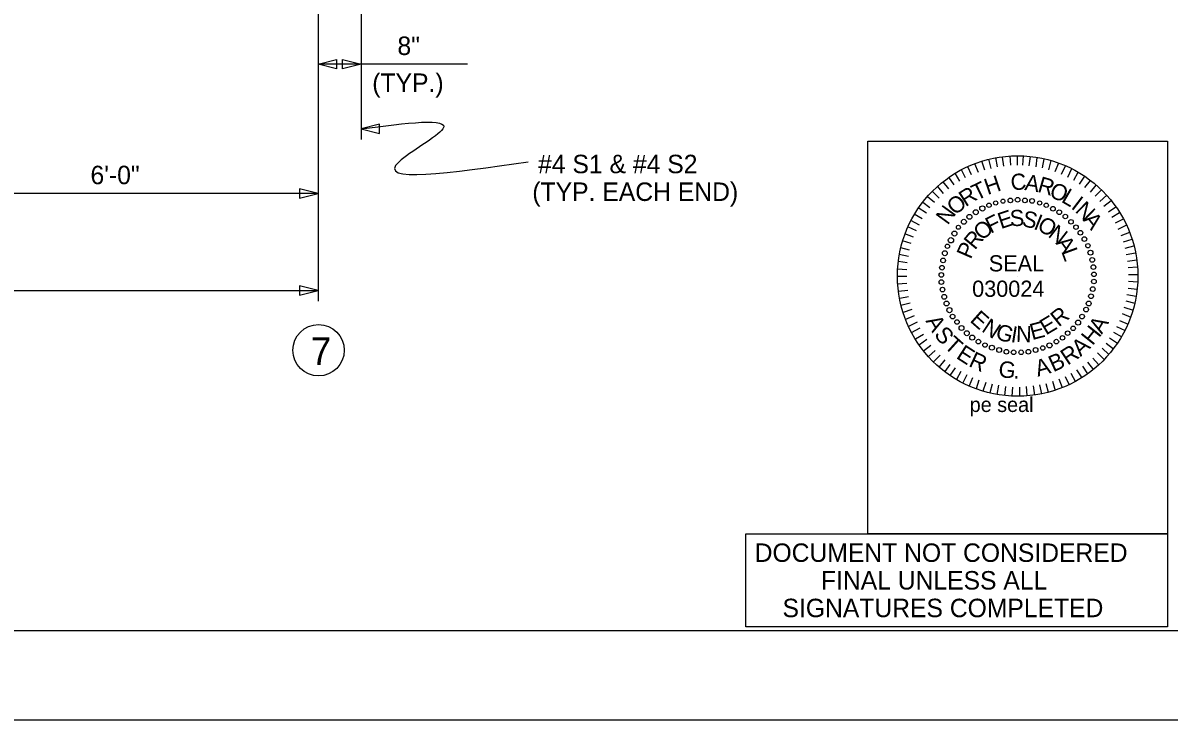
# Model space of a CAD drawing. Extents: x -41 to 251, y -169 to 237.
# Drawn here: x 46.48 to 64.22, y -50.47 to -39.68 of the extents above; entities that cross this region are included whole.
import ezdxf

# ---------------------------------------------------------------- set-up
doc = ezdxf.new("R2010")
doc.units = 0
for name, color, linetype in [('Arrowhead Terminators', 7, 'Continuous'), ('Arrowhead Terminators CELL', 7, 'Continuous'), ('Dimension Lines', 7, 'Continuous'), ('Peseal', 7, 'Continuous'), ('Plan Sheet CELL', 7, 'Continuous'), ('Plot Shape CELL', 7, 'Continuous'), ('Sheet Sticker Exception Certification CELL', 7, 'Continuous'), ('Text', 7, 'Continuous'), ('Title Text', 7, 'Continuous'), ('User Information Notes', 7, 'Continuous'), ('User Information Notes CELL', 7, 'Continuous')]:
    doc.layers.add(name, color=color, linetype=linetype)

msp = doc.modelspace()

# ---------------------------------------------------------------- linework, layer by layer
at = {"layer": 'Arrowhead Terminators'}
msp.add_lwpolyline([(50.763, -42.387), (51.049, -42.315), (50.763, -42.244)], close=True, dxfattribs=at)
at = {"layer": 'Arrowhead Terminators CELL'}
for points in [[(51.049, -40.315), (51.335, -40.244), (51.335, -40.387)], [(51.715, -40.315), (51.429, -40.387), (51.429, -40.244)], [(51.715, -41.315), (52.001, -41.387), (52.001, -41.244)], [(51.049, -43.815), (50.762, -43.744), (50.762, -43.887)]]:
    msp.add_lwpolyline(points, close=True, dxfattribs=at)
at = {"layer": 'Dimension Lines'}
for p, q in [((51.715, -36.492), (51.715, -41.482)), ((51.049, -36.565), (51.049, -43.982)), ((51.715, -40.315), (51.049, -40.315)), ((53.361, -40.315), (51.715, -40.315)), ((51.049, -42.315), (45.049, -42.315)), ((39.049, -43.815), (51.049, -43.815))]:
    msp.add_line(p, q, dxfattribs=at)
msp.add_circle((51.056, -44.742), 0.397, dxfattribs=at)
msp.add_spline([(51.715, -41.315), (52.98, -41.315), (52.302, -41.823), (54.3, -41.823)], degree=3, dxfattribs=at)
at = {"layer": 'Peseal'}
for p, q in [((61.268, -41.992), (61.214, -41.858)), ((61.366, -41.956), (61.321, -41.813)), ((61.465, -41.93), (61.429, -41.786)), ((61.563, -41.903), (61.536, -41.76)), ((61.661, -41.894), (61.643, -41.751)), ((61.769, -41.876), (61.76, -41.733)), ((61.876, -41.876), (61.876, -41.733)), ((61.957, -41.876), (61.965, -41.733)), ((62.055, -41.885), (62.073, -41.742)), ((62.162, -41.903), (62.18, -41.76)), ((62.261, -41.921), (62.288, -41.777)), ((62.359, -41.947), (62.395, -41.804)), ((62.457, -41.974), (62.511, -41.84)), ((60.981, -42.126), (60.91, -42.001)), ((61.071, -42.073), (61.008, -41.947)), ((61.16, -42.028), (61.107, -41.903)), ((62.556, -42.019), (62.618, -41.885)), ((62.654, -42.064), (62.717, -41.93)), ((62.744, -42.108), (62.815, -41.983)), ((60.731, -42.314), (60.642, -42.207)), ((60.812, -42.243), (60.722, -42.135)), ((60.892, -42.18), (60.812, -42.064)), ((62.833, -42.171), (62.914, -42.046)), ((62.914, -42.225), (63.003, -42.117)), ((63.003, -42.296), (63.093, -42.189)), ((60.588, -42.457), (60.481, -42.368)), ((60.659, -42.386), (60.552, -42.278)), ((63.075, -42.359), (63.173, -42.261)), ((63.146, -42.439), (63.254, -42.341)), ((60.463, -42.618), (60.337, -42.538)), ((60.516, -42.538), (60.409, -42.457)), ((63.209, -42.511), (63.325, -42.422)), ((63.28, -42.6), (63.397, -42.52)), ((60.355, -42.806), (60.221, -42.735)), ((60.4, -42.708), (60.275, -42.636)), ((63.334, -42.681), (63.45, -42.609)), ((63.388, -42.77), (63.513, -42.708)), ((60.311, -42.896), (60.176, -42.833)), ((63.433, -42.869), (63.558, -42.806)), ((63.477, -42.967), (63.611, -42.914)), ((60.23, -43.092), (60.096, -43.048)), ((60.266, -42.994), (60.132, -42.94)), ((63.513, -43.066), (63.647, -43.021)), ((60.185, -43.289), (60.042, -43.262)), ((60.203, -43.191), (60.069, -43.155)), ((63.54, -43.164), (63.674, -43.128)), ((63.558, -43.262), (63.701, -43.236)), ((60.167, -43.388), (60.033, -43.37)), ((63.576, -43.361), (63.719, -43.343)), ((63.585, -43.459), (63.728, -43.45)), ((60.159, -43.495), (60.015, -43.486)), ((60.159, -43.602), (60.015, -43.602)), ((63.594, -43.567), (63.737, -43.567)), ((60.159, -43.71), (60.015, -43.719)), ((63.585, -43.781), (63.728, -43.799)), ((63.594, -43.674), (63.737, -43.683)), ((60.176, -43.817), (60.033, -43.835)), ((60.185, -43.915), (60.051, -43.942)), ((63.549, -43.978), (63.692, -44.014)), ((63.567, -43.88), (63.71, -43.906)), ((60.212, -44.014), (60.069, -44.05)), ((60.239, -44.112), (60.105, -44.157)), ((63.522, -44.076), (63.665, -44.121)), ((60.275, -44.211), (60.141, -44.264)), ((60.32, -44.309), (60.185, -44.372)), ((63.45, -44.282), (63.585, -44.336)), ((63.495, -44.175), (63.629, -44.229)), ((60.364, -44.398), (60.23, -44.47)), ((60.418, -44.497), (60.293, -44.568)), ((63.361, -44.461), (63.486, -44.533)), ((63.406, -44.372), (63.54, -44.434)), ((60.472, -44.577), (60.355, -44.658)), ((60.534, -44.667), (60.418, -44.756)), ((63.245, -44.631), (63.361, -44.721)), ((63.298, -44.551), (63.424, -44.631)), ((60.597, -44.747), (60.498, -44.837)), ((60.677, -44.819), (60.57, -44.926)), ((63.039, -44.864), (63.128, -44.962)), ((63.11, -44.783), (63.218, -44.89)), ((63.182, -44.712), (63.289, -44.81)), ((60.749, -44.89), (60.659, -44.998)), ((60.829, -44.962), (60.749, -45.069)), ((60.91, -45.016), (60.829, -45.132)), ((62.788, -45.043), (62.869, -45.168)), ((62.878, -44.989), (62.958, -45.105)), ((62.958, -44.926), (63.048, -45.043)), ((60.999, -45.069), (60.928, -45.195)), ((61.089, -45.123), (61.026, -45.248)), ((61.178, -45.168), (61.125, -45.293)), ((61.277, -45.204), (61.232, -45.338)), ((62.413, -45.221), (62.457, -45.365)), ((62.511, -45.186), (62.565, -45.32)), ((62.61, -45.15), (62.672, -45.275)), ((62.699, -45.096), (62.771, -45.23)), ((61.384, -45.239), (61.339, -45.374)), ((61.482, -45.266), (61.447, -45.4)), ((61.581, -45.284), (61.554, -45.427)), ((61.688, -45.302), (61.67, -45.445)), ((61.796, -45.311), (61.787, -45.454)), ((61.903, -45.311), (61.903, -45.454)), ((62.01, -45.302), (62.019, -45.445)), ((62.118, -45.293), (62.135, -45.436)), ((62.216, -45.275), (62.243, -45.418)), ((62.314, -45.257), (62.35, -45.391))]:
    msp.add_line(p, q, dxfattribs=at)
for centre, radius in [((61.764, -42.422), 0.0361), ((61.876, -42.413), 0.0358), ((61.988, -42.422), 0.0361), ((62.1, -42.431), 0.0369), ((61.227, -42.605), 0.0385), ((61.33, -42.547), 0.04), ((61.433, -42.498), 0.0341), ((61.536, -42.462), 0.0326), ((61.648, -42.435), 0.0316), ((62.216, -42.462), 0.0326), ((62.319, -42.498), 0.0341), ((62.422, -42.551), 0.0361), ((62.52, -42.605), 0.0361), ((61.044, -42.753), 0.038), ((61.129, -42.677), 0.0385), ((62.614, -42.672), 0.0349), ((62.703, -42.753), 0.0349), ((60.897, -42.936), 0.0385), ((60.959, -42.838), 0.0316), ((62.78, -42.838), 0.0349), ((62.847, -42.923), 0.0361), ((60.789, -43.133), 0.0341), ((60.843, -43.039), 0.0412), ((62.909, -43.021), 0.0361), ((62.963, -43.124), 0.0341), ((60.749, -43.24), 0.0382), ((63.003, -43.231), 0.0382), ((60.704, -43.464), 0.0361), ((60.722, -43.352), 0.0369), ((63.03, -43.343), 0.0369), ((63.048, -43.455), 0.0361), ((60.695, -43.576), 0.0358), ((63.057, -43.567), 0.0358), ((60.695, -43.687), 0.0361), ((60.713, -43.804), 0.0361), ((63.039, -43.795), 0.0361), ((63.057, -43.678), 0.0361), ((60.74, -43.915), 0.0369), ((60.776, -44.018), 0.0382), ((62.976, -44.018), 0.0382), ((63.012, -43.906), 0.0369), ((60.82, -44.121), 0.04), ((62.936, -44.112), 0.0361), ((60.87, -44.22), 0.0361), ((60.937, -44.305), 0.0349), ((62.811, -44.314), 0.0385), ((62.873, -44.22), 0.0361), ((61.008, -44.398), 0.038), ((61.089, -44.479), 0.038), ((61.174, -44.546), 0.0385), ((62.569, -44.551), 0.0349), ((62.65, -44.479), 0.0349), ((62.735, -44.403), 0.0349), ((61.268, -44.609), 0.0361), ((61.371, -44.662), 0.0341), ((61.478, -44.703), 0.0382), ((61.59, -44.738), 0.0369), ((62.153, -44.738), 0.0369), ((62.265, -44.707), 0.0341), ((62.368, -44.667), 0.04), ((62.475, -44.609), 0.0361), ((61.702, -44.765), 0.0361), ((61.813, -44.774), 0.0358), ((61.93, -44.774), 0.0358), ((62.042, -44.765), 0.0361)]:
    msp.add_circle(centre, radius, dxfattribs=at)
at = {"layer": 'Plan Sheet CELL'}
msp.add_line((2.414, -49.079), (75.694, -49.079), dxfattribs=at)
at = {"layer": 'Plot Shape CELL'}
msp.add_lwpolyline([(0, -0.087), (75.715, -0.087), (75.715, -50.467), (0, -50.467)], close=True, dxfattribs=at)
at = {"layer": 'Sheet Sticker Exception Certification CELL'}
msp.add_lwpolyline([(57.671, -47.586), (64.195, -47.586), (64.195, -49.021), (57.671, -49.021)], close=True, dxfattribs=at)
at = {"layer": 'User Information Notes'}
msp.add_line((61.876, -43.593), (61.876, -43.593), dxfattribs=at)
at = {"layer": 'User Information Notes CELL'}
msp.add_line((61.876, -43.593), (61.876, -43.593), dxfattribs=at)
msp.add_lwpolyline([(59.557, -41.504), (64.195, -41.504), (64.195, -47.586), (59.557, -47.586)], close=True, dxfattribs=at)
msp.add_circle((61.876, -43.593), 1.861, dxfattribs=at)

# ---------------------------------------------------------------- texts
at = {"layer": 'Peseal'}
for s, height, rotation, p in [('H', 0.25, 18.9162, (61.411, -42.341)), ('C', 0.25, 4.8625, (61.778, -42.269)), ('A', 0.25, 350.8088, (61.974, -42.261)), ('T', 0.25, 25.943, (61.241, -42.431)), ('R', 0.25, 343.7819, (62.171, -42.287)), ('O', 0.25, 336.7551, (62.35, -42.359)), ('O', 0.25, 39.9967, (60.91, -42.663)), ('R', 0.25, 32.9699, (61.071, -42.529)), ('L', 0.25, 329.7282, (62.538, -42.439)), ('I', 0.25, 322.7014, (62.69, -42.538)), ('N', 0.25, 54.0504, (60.794, -42.815)), ('E', 0.25, 18.4448, (61.617, -42.869)), ('S', 0.25, 2.3789, (61.76, -42.824)), ('N', 0.25, 315.6745, (62.753, -42.592)), ('O', 0.25, 42.5436, (61.33, -43.057)), ('F', 0.25, 26.4777, (61.456, -42.94)), ('S', 0.25, 346.313, (61.93, -42.815)), ('I', 0.25, 338.28, (62.109, -42.86)), ('O', 0.25, 330.2471, (62.162, -42.869)), ('A', 0.25, 308.6477, (62.878, -42.726)), ('R', 0.25, 50.5765, (61.214, -43.2)), ('N', 0.25, 322.2141, (62.332, -42.976)), ('P', 0.25, 66.6424, (61.151, -43.343)), ('A', 0.25, 306.1483, (62.457, -43.084)), ('L', 0.25, 290.0824, (62.547, -43.209)), ('E', 0.25, 318.5179, (61.125, -44.291)), ('R', 0.25, 38.6997, (62.511, -44.39)), ('A', 0.254, 300.3993, (60.445, -44.288)), ('N', 0.25, 326.5361, (61.304, -44.443)), ('G', 0.25, 342.5725, (61.518, -44.56)), ('E', 0.25, 14.6452, (62.1, -44.586)), ('E', 0.25, 30.6815, (62.314, -44.515)), ('A', 0.254, 59.6007, (63.18, -44.503)), ('S', 0.254, 309.4349, (60.572, -44.504)), ('T', 0.254, 318.1096, (60.724, -44.69)), ('I', 0.25, 350.5906, (61.76, -44.613)), ('N', 0.25, 358.6088, (61.849, -44.613)), ('H', 0.254, 51.3597, (63.036, -44.681)), ('E', 0.254, 327.1453, (60.911, -44.857)), ('R', 0.254, 33.5776, (62.649, -44.983)), ('A', 0.254, 42.3241, (62.851, -44.85)), ('R', 0.254, 335.458, (61.104, -44.984)), ('A', 0.254, 15.7955, (62.187, -45.153)), ('B', 0.254, 24.8312, (62.428, -45.085)), ('G', 0.254, 353.3858, (61.569, -45.154)), ('.', 0.254, 2.1323, (61.81, -45.182))]:
    msp.add_text(s, height=height, rotation=rotation, dxfattribs=at).set_placement(p)
for s, p in [('SEAL', (61.429, -43.522)), ('030024', (61.172, -43.915))]:
    msp.add_text(s, height=0.2505, dxfattribs=at).set_placement(p)
at = {"layer": 'Sheet Sticker Exception Certification CELL'}
for s, p in [('DOCUMENT NOT CONSIDERED', (57.806, -48.018)), ('FINAL UNLESS ALL', (58.832, -48.446)), ('SIGNATURES COMPLETED', (58.237, -48.874))]:
    msp.add_text(s, height=0.28561, dxfattribs=at).set_placement(p)
at = {"layer": 'Text'}
for s, p in [('8"', (52.277, -40.172)), ('(TYP.)', (51.887, -40.744)), ('#4 S1 & #4 S2', (54.454, -42.002)), ('6\'-0"', (47.526, -42.172)), ('(TYP. EACH END)', (54.364, -42.431))]:
    msp.add_text(s, height=0.286, dxfattribs=at).set_placement(p)
at = {"layer": 'Title Text'}
msp.add_text('7', height=0.429, dxfattribs=at).set_placement((50.934, -44.972))
at = {"layer": 'User Information Notes CELL'}
msp.add_text('pe seal', height=0.229, dxfattribs=at).set_placement((61.134, -45.698))

doc.saveas('drawing.dxf')
